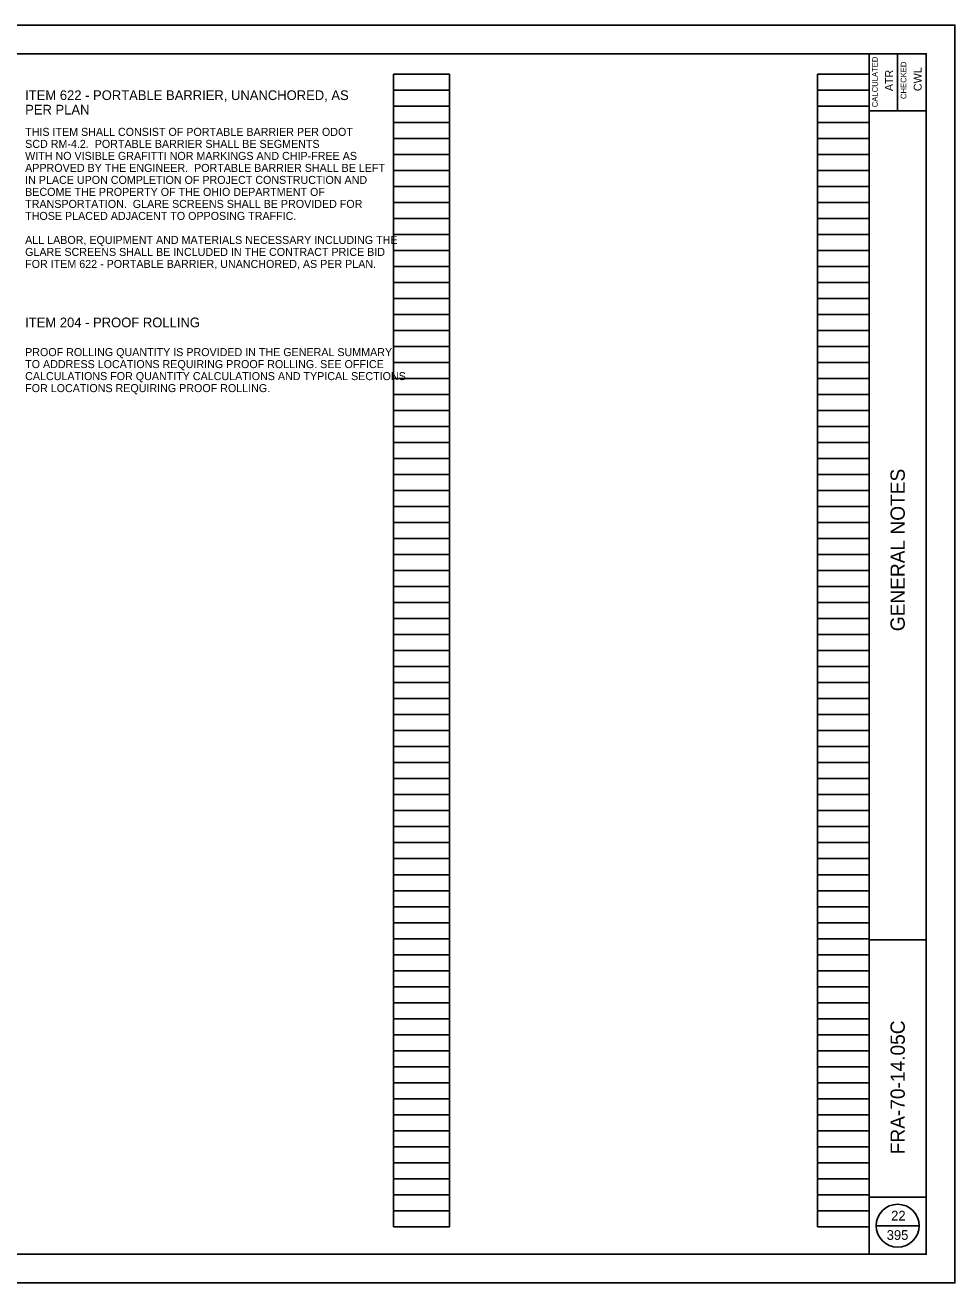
# Model space of a CAD drawing. Extents: x 0 to 34, y 0 to 22.
# Drawn here: x 17.74 to 34, y 0 to 22 of the extents above; entities that cross this region are included whole.
import ezdxf

# ---------------------------------------------------------------- set-up
doc = ezdxf.new("R2010")
doc.units = 0
for name, color, linetype in [('SC_Scratch1', 7, 'Continuous'), ('SH_Border', 7, 'Continuous'), ('SH_Cut_Line', 7, 'Continuous'), ('SH_Data', 7, 'Continuous'), ('SH_Text', 7, 'Continuous'), ('TX_P_Misc', 7, 'Continuous')]:
    doc.layers.add(name, color=color, linetype=linetype)

msp = doc.modelspace()

# ---------------------------------------------------------------- linework, layer by layer
at = {"layer": 'SC_Scratch1'}
for p, q in [((24.18, 0.98), (24.18, 21.14)), ((24.18, 21.14), (25.16, 21.14)), ((25.16, 0.98), (25.16, 21.14)), ((31.6, 0.98), (31.6, 21.14)), ((31.6, 21.14), (32.5, 21.14)), ((32.5, 0.98), (32.5, 21.14)), ((24.18, 20.86), (25.16, 20.86)), ((31.6, 20.86), (32.5, 20.86)), ((24.18, 20.58), (25.16, 20.58)), ((31.6, 20.58), (32.5, 20.58)), ((24.18, 20.3), (25.16, 20.3)), ((31.6, 20.3), (32.5, 20.3)), ((24.18, 20.02), (25.16, 20.02)), ((31.6, 20.02), (32.5, 20.02)), ((24.18, 19.74), (25.16, 19.74)), ((31.6, 19.74), (32.5, 19.74)), ((24.18, 19.46), (25.16, 19.46)), ((31.6, 19.46), (32.5, 19.46)), ((24.18, 19.18), (25.16, 19.18)), ((31.6, 19.18), (32.5, 19.18)), ((24.18, 18.9), (25.16, 18.9)), ((31.6, 18.9), (32.5, 18.9)), ((24.18, 18.62), (25.16, 18.62)), ((31.6, 18.62), (32.5, 18.62)), ((24.18, 18.34), (25.16, 18.34)), ((31.6, 18.34), (32.5, 18.34)), ((24.18, 18.06), (25.16, 18.06)), ((31.6, 18.06), (32.5, 18.06)), ((24.18, 17.78), (25.16, 17.78)), ((31.6, 17.78), (32.5, 17.78)), ((24.18, 17.5), (25.16, 17.5)), ((31.6, 17.5), (32.5, 17.5)), ((24.18, 17.22), (25.16, 17.22)), ((31.6, 17.22), (32.5, 17.22)), ((24.18, 16.94), (25.16, 16.94)), ((31.6, 16.94), (32.5, 16.94)), ((24.18, 16.66), (25.16, 16.66)), ((31.6, 16.66), (32.5, 16.66)), ((24.18, 16.38), (25.16, 16.38)), ((31.6, 16.38), (32.5, 16.38)), ((24.18, 16.1), (25.16, 16.1)), ((31.6, 16.1), (32.5, 16.1)), ((24.18, 15.82), (25.16, 15.82)), ((31.6, 15.82), (32.5, 15.82)), ((24.18, 15.54), (25.16, 15.54)), ((31.6, 15.54), (32.5, 15.54)), ((24.18, 15.26), (25.16, 15.26)), ((31.6, 15.26), (32.5, 15.26)), ((24.18, 14.98), (25.16, 14.98)), ((31.6, 14.98), (32.5, 14.98)), ((24.18, 14.7), (25.16, 14.7)), ((31.6, 14.7), (32.5, 14.7)), ((24.18, 14.42), (25.16, 14.42)), ((31.6, 14.42), (32.5, 14.42)), ((24.18, 14.14), (25.16, 14.14)), ((31.6, 14.14), (32.5, 14.14)), ((24.18, 13.86), (25.16, 13.86)), ((31.6, 13.86), (32.5, 13.86)), ((24.18, 13.58), (25.16, 13.58)), ((31.6, 13.58), (32.5, 13.58)), ((24.18, 13.3), (25.16, 13.3)), ((31.6, 13.3), (32.5, 13.3)), ((24.18, 13.02), (25.16, 13.02)), ((31.6, 13.02), (32.5, 13.02)), ((24.18, 12.74), (25.16, 12.74)), ((31.6, 12.74), (32.5, 12.74)), ((24.18, 12.46), (25.16, 12.46)), ((31.6, 12.46), (32.5, 12.46)), ((24.18, 12.18), (25.16, 12.18)), ((31.6, 12.18), (32.5, 12.18)), ((24.18, 11.9), (25.16, 11.9)), ((31.6, 11.9), (32.5, 11.9)), ((24.18, 11.62), (25.16, 11.62)), ((31.6, 11.62), (32.5, 11.62)), ((24.18, 11.34), (25.16, 11.34)), ((31.6, 11.34), (32.5, 11.34)), ((24.18, 11.06), (25.16, 11.06)), ((31.6, 11.06), (32.5, 11.06)), ((24.18, 10.78), (25.16, 10.78)), ((31.6, 10.78), (32.5, 10.78)), ((24.18, 10.5), (25.16, 10.5)), ((31.6, 10.5), (32.5, 10.5)), ((24.18, 10.22), (25.16, 10.22)), ((31.6, 10.22), (32.5, 10.22)), ((24.18, 9.94), (25.16, 9.94)), ((31.6, 9.94), (32.5, 9.94)), ((24.18, 9.66), (25.16, 9.66)), ((31.6, 9.66), (32.5, 9.66)), ((24.18, 9.38), (25.16, 9.38)), ((31.6, 9.38), (32.5, 9.38)), ((24.18, 9.1), (25.16, 9.1)), ((31.6, 9.1), (32.5, 9.1)), ((24.18, 8.82), (25.16, 8.82)), ((31.6, 8.82), (32.5, 8.82)), ((24.18, 8.54), (25.16, 8.54)), ((31.6, 8.54), (32.5, 8.54)), ((24.18, 8.26), (25.16, 8.26)), ((31.6, 8.26), (32.5, 8.26)), ((24.18, 7.98), (25.16, 7.98)), ((31.6, 7.98), (32.5, 7.98)), ((24.18, 7.7), (25.16, 7.7)), ((31.6, 7.7), (32.5, 7.7)), ((24.18, 7.42), (25.16, 7.42)), ((31.6, 7.42), (32.5, 7.42)), ((24.18, 7.14), (25.16, 7.14)), ((31.6, 7.14), (32.5, 7.14)), ((24.18, 6.86), (25.16, 6.86)), ((31.6, 6.86), (32.5, 6.86)), ((24.18, 6.58), (25.16, 6.58)), ((31.6, 6.58), (32.5, 6.58)), ((24.18, 6.3), (25.16, 6.3)), ((31.6, 6.3), (32.5, 6.3)), ((24.18, 6.02), (25.16, 6.02)), ((31.6, 6.02), (32.5, 6.02)), ((24.18, 5.74), (25.16, 5.74)), ((31.6, 5.74), (32.5, 5.74)), ((24.18, 5.46), (25.16, 5.46)), ((31.6, 5.46), (32.5, 5.46)), ((24.18, 5.18), (25.16, 5.18)), ((31.6, 5.18), (32.5, 5.18)), ((24.18, 4.9), (25.16, 4.9)), ((31.6, 4.9), (32.5, 4.9)), ((24.18, 4.62), (25.16, 4.62)), ((31.6, 4.62), (32.5, 4.62)), ((24.18, 4.34), (25.16, 4.34)), ((31.6, 4.34), (32.5, 4.34)), ((24.18, 4.06), (25.16, 4.06)), ((31.6, 4.06), (32.5, 4.06)), ((24.18, 3.78), (25.16, 3.78)), ((31.6, 3.78), (32.5, 3.78)), ((24.18, 3.5), (25.16, 3.5)), ((31.6, 3.5), (32.5, 3.5)), ((24.18, 3.22), (25.16, 3.22)), ((31.6, 3.22), (32.5, 3.22)), ((24.18, 2.94), (25.16, 2.94)), ((31.6, 2.94), (32.5, 2.94)), ((24.18, 2.66), (25.16, 2.66)), ((31.6, 2.66), (32.5, 2.66)), ((24.18, 2.38), (25.16, 2.38)), ((31.6, 2.38), (32.5, 2.38)), ((24.18, 2.1), (25.16, 2.1)), ((31.6, 2.1), (32.5, 2.1)), ((24.18, 1.82), (25.16, 1.82)), ((31.6, 1.82), (32.5, 1.82)), ((24.18, 1.54), (25.16, 1.54)), ((31.6, 1.54), (32.5, 1.54)), ((24.18, 1.26), (25.16, 1.26)), ((31.6, 1.26), (32.5, 1.26)), ((24.18, 0.98), (25.16, 0.98)), ((31.6, 0.98), (32.5, 0.98))]:
    msp.add_line(p, q, dxfattribs=at)
at = {"layer": 'SH_Border'}
for p, q in [((32.5, 0.5), (32.5, 21.5)), ((33, 21.5), (33, 20.5)), ((32.5, 20.5), (33.5, 20.5)), ((32.5, 6), (33.5, 6)), ((32.5, 1.5), (33.5, 1.5))]:
    msp.add_line(p, q, dxfattribs=at)
msp.add_lwpolyline([(2, 21.5), (33.5, 21.5), (33.5, 0.5), (2, 0.5)], close=True, dxfattribs=at)
at = {"layer": 'SH_Cut_Line'}
msp.add_lwpolyline([(0, 0), (34, 0), (34, 22), (0, 22)], close=True, dxfattribs=at)
at = {"layer": 'SH_Data'}
msp.add_line((32.625, 1), (33.375, 1), dxfattribs=at)
msp.add_circle((33, 1), 0.375, dxfattribs=at)

# ---------------------------------------------------------------- texts
for s, height, p in [('CALCULATED', 0.1, (32.652, 20.565)), ('CHECKED', 0.1, (33.152, 20.708)), ('ATR', 0.14, (32.92, 20.846)), ('CWL', 0.14, (33.42, 20.846)), ('GENERAL NOTES', 0.25, (33.125, 11.398)), ('FRA-70-14.05C', 0.25, (33.125, 2.249))]:
    msp.add_text(s, height=height, rotation=90, dxfattribs=at).set_placement(p)
for s, p in [('22', (32.886, 1.09)), ('395', (32.808, 0.752))]:
    msp.add_text(s, height=0.17, dxfattribs=at).set_placement(p)
at = {"layer": 'SH_Text'}
for s, p in [('THIS ITEM SHALL CONSIST OF PORTABLE BARRIER PER ODOT ', (17.74, 20.063)), ('SCD RM-4.2.  PORTABLE BARRIER SHALL BE SEGMENTS ', (17.74, 19.853)), ('WITH NO VISIBLE GRAFITTI NOR MARKINGS AND CHIP-FREE AS ', (17.74, 19.643)), ('APPROVED BY THE ENGINEER.  PORTABLE BARRIER SHALL BE LEFT ', (17.74, 19.433)), ('IN PLACE UPON COMPLETION OF PROJECT CONSTRUCTION AND ', (17.74, 19.223)), ('BECOME THE PROPERTY OF THE OHIO DEPARTMENT OF ', (17.74, 19.013)), ('TRANSPORTATION.  GLARE SCREENS SHALL BE PROVIDED FOR ', (17.74, 18.803)), ('THOSE PLACED ADJACENT TO OPPOSING TRAFFIC.', (17.74, 18.593)), ('ALL LABOR, EQUIPMENT AND MATERIALS NECESSARY INCLUDING THE', (17.74, 18.173)), ('GLARE SCREENS SHALL BE INCLUDED IN THE CONTRACT PRICE BID ', (17.74, 17.963)), ('FOR ITEM 622 - PORTABLE BARRIER, UNANCHORED, AS PER PLAN.', (17.74, 17.753)), ('PROOF ROLLING QUANTITY IS PROVIDED IN THE GENERAL SUMMARY ', (17.74, 16.211)), ('TO ADDRESS LOCATIONS REQUIRING PROOF ROLLING. SEE OFFICE ', (17.74, 16.001)), ('CALCULATIONS FOR QUANTITY CALCULATIONS AND TYPICAL SECTIONS ', (17.74, 15.791)), ('FOR LOCATIONS REQUIRING PROOF ROLLING.', (17.74, 15.581))]:
    msp.add_text(s, height=0.14, dxfattribs=at).set_placement(p)
at = {"layer": 'TX_P_Misc'}
for s, p in [('ITEM 622 - PORTABLE BARRIER, UNANCHORED, AS ', (17.74, 20.69)), ('PER PLAN', (17.74, 20.437)), ('ITEM 204 - PROOF ROLLING', (17.74, 16.715))]:
    msp.add_text(s, height=0.17, dxfattribs=at).set_placement(p)

doc.saveas('drawing.dxf')
